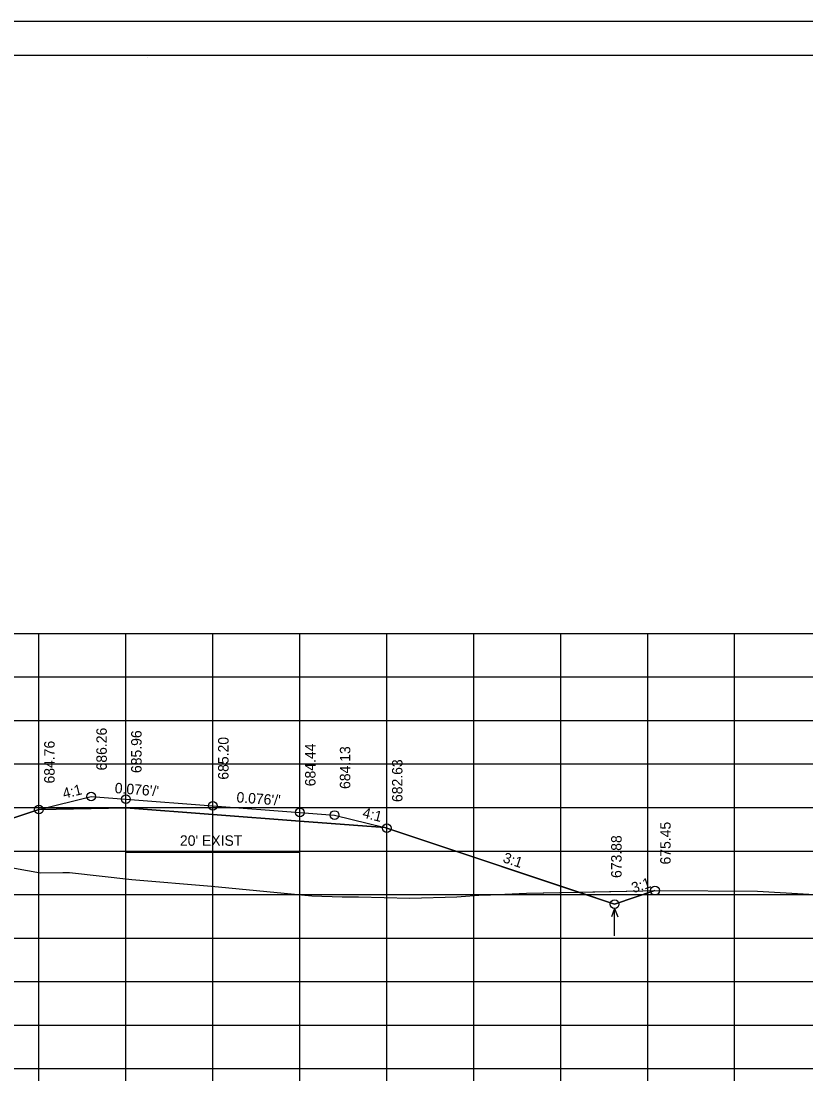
# Model space of a CAD drawing. Extents: x 1360146 to 1361431, y 631444 to 632352.
# Drawn here: x 1360296.7 to 1360386.9, y 631748.4 to 631870.8 of the extents above; entities that cross this region are included whole.
import ezdxf

# ---------------------------------------------------------------- set-up
doc = ezdxf.new("R2010")
doc.units = 0
for name, color, linetype in [('Default', 7, 'Continuous'), ('R_Alt Surface', 7, 'Continuous'), ('R_Axis', 7, 'Continuous'), ('R_Border', 7, 'Continuous'), ('R_Exist Surface', 7, 'Continuous'), ('R_Fin Surface', 7, 'Continuous'), ('R_Grid', 7, 'Continuous'), ('R_No Plot', 7, 'Continuous'), ('R_Water Annot', 7, 'Continuous'), ('R_Xsect Elev', 7, 'Continuous'), ('R_Xsect Slope', 7, 'Continuous')]:
    doc.layers.add(name, color=color, linetype=linetype)

msp = doc.modelspace()

# ---------------------------------------------------------------- linework, layer by layer
at = {"layer": 'Default'}
for p, q in [((1360308.77, 631774.69), (1360308.77, 631776.06)), ((1360328.77, 631774.69), (1360328.77, 631776.06)), ((1360308.77, 631775.35), (1360328.77, 631775.35))]:
    msp.add_line(p, q, dxfattribs=at)
at = {"layer": 'R_Alt Surface'}
msp.add_lwpolyline([(1360298.75, 631780.24), (1360308.77, 631780.44), (1360318.77, 631779.68), (1360328.77, 631778.92), (1360338.55, 631778.17)], dxfattribs=at)
at = {"layer": 'R_Axis'}
for p, q in [((1360178.77, 631750.48), (1360458.77, 631750.48)), ((1360298.77, 631749.08), (1360298.77, 631750.48)), ((1360308.77, 631749.08), (1360308.77, 631750.48)), ((1360318.77, 631749.08), (1360318.77, 631750.48)), ((1360328.77, 631749.08), (1360328.77, 631750.48)), ((1360338.77, 631749.08), (1360338.77, 631750.48)), ((1360348.77, 631749.08), (1360348.77, 631750.48)), ((1360358.77, 631749.08), (1360358.77, 631750.48)), ((1360368.77, 631749.08), (1360368.77, 631750.48)), ((1360378.77, 631749.08), (1360378.77, 631750.48))]:
    msp.add_line(p, q, dxfattribs=at)
at = {"layer": 'R_Border'}
for p, q in [((1360158.77, 631866.94), (1360474.95, 631866.94)), ((1360311.29, 631866.68), (1360311.29, 631866.68)), ((1360311.29, 631866.68), (1360311.29, 631866.68))]:
    msp.add_line(p, q, dxfattribs=at)
at = {"layer": 'R_Exist Surface'}
msp.add_lwpolyline([(1360290.37, 631774.5), (1360298.93, 631772.97), (1360301.53, 631773.02), (1360302.27, 631773.02), (1360309.44, 631772.21), (1360318.61, 631771.43), (1360330.16, 631770.31), (1360333.64, 631770.2), (1360335.53, 631770.21), (1360341.41, 631770.06), (1360346.84, 631770.23), (1360349.86, 631770.43), (1360350.68, 631770.45), (1360354.83, 631770.62), (1360368.2, 631770.91), (1360370.03, 631770.93), (1360381.41, 631770.85), (1360387.29, 631770.51)], dxfattribs=at)
at = {"layer": 'R_Fin Surface'}
msp.add_lwpolyline([(1360246.93, 631773.2), (1360262.28, 631768.08), (1360298.75, 631780.24), (1360298.77, 631780.24), (1360304.77, 631781.74), (1360308.77, 631781.44), (1360318.77, 631780.68), (1360328.77, 631779.92), (1360332.77, 631779.61), (1360338.55, 631778.17), (1360338.77, 631778.11), (1360364.97, 631769.38), (1360369.61, 631770.93)], dxfattribs=at)
at = {"layer": 'R_Grid'}
for p, q in [((1360178.77, 631800.48), (1360458.77, 631800.48)), ((1360298.77, 631750.48), (1360298.77, 631800.48)), ((1360308.77, 631750.48), (1360308.77, 631800.48)), ((1360318.77, 631750.48), (1360318.77, 631800.48)), ((1360328.77, 631750.48), (1360328.77, 631800.48)), ((1360338.77, 631750.48), (1360338.77, 631800.48)), ((1360348.77, 631750.48), (1360348.77, 631800.48)), ((1360358.77, 631750.48), (1360358.77, 631800.48)), ((1360368.77, 631750.48), (1360368.77, 631800.48)), ((1360378.77, 631750.48), (1360378.77, 631800.48)), ((1360178.77, 631795.48), (1360458.77, 631795.48)), ((1360178.77, 631790.48), (1360458.77, 631790.48)), ((1360178.77, 631785.48), (1360458.77, 631785.48)), ((1360178.77, 631780.48), (1360458.77, 631780.48)), ((1360178.77, 631775.48), (1360458.77, 631775.48)), ((1360178.77, 631770.48), (1360458.77, 631770.48)), ((1360178.77, 631765.48), (1360458.77, 631765.48)), ((1360178.77, 631760.48), (1360458.77, 631760.48)), ((1360178.77, 631755.48), (1360458.77, 631755.48)), ((1360178.77, 631750.48), (1360458.77, 631750.48))]:
    msp.add_line(p, q, dxfattribs=at)
at = {"layer": 'R_No Plot'}
msp.add_line((1360146.37, 631870.84), (1360479.7, 631870.84), dxfattribs=at)
for points in [[(1360146.36, 631870.84), (1360479.7, 631870.84), (1360479.7, 631657.5), (1360146.36, 631657.5)], [(1360392.69, 631866.94), (1360392.69, 631857.06), (1360428.42, 631857.06), (1360428.42, 631854.14), (1360451.62, 631854.14), (1360451.62, 631829.81), (1360474.95, 631829.81), (1360474.95, 631661.48), (1360158.77, 631661.48), (1360158.77, 631866.94)], [(1360360.86, 631770.75), (1360368.2, 631770.91), (1360369.61, 631770.93), (1360364.97, 631769.38)]]:
    msp.add_lwpolyline(points, close=True, dxfattribs=at)
msp.add_lwpolyline([(1360290.37, 631774.5), (1360298.93, 631772.97), (1360301.53, 631773.02), (1360302.27, 631773.02), (1360309.44, 631772.21), (1360318.61, 631771.43), (1360330.16, 631770.31), (1360333.64, 631770.2), (1360335.53, 631770.21), (1360341.41, 631770.06), (1360346.84, 631770.23), (1360349.86, 631770.43), (1360350.68, 631770.45), (1360354.83, 631770.62), (1360360.86, 631770.75), (1360338.77, 631778.11), (1360338.55, 631778.17), (1360328.77, 631778.92), (1360318.77, 631779.68), (1360308.77, 631780.44), (1360298.75, 631780.24), (1360281.82, 631774.6)], dxfattribs=at)
for centre in [(1360304.77, 631781.74), (1360308.77, 631781.44), (1360298.77, 631780.24), (1360318.77, 631780.68), (1360328.77, 631779.92), (1360332.77, 631779.61), (1360338.77, 631778.11), (1360369.61, 631770.93), (1360364.97, 631769.38)]:
    msp.add_circle(centre, 0.5, dxfattribs=at)
at = {"layer": 'R_Water Annot'}
for p, q in [((1360364.97, 631768.88), (1360364.62, 631767.92)), ((1360364.97, 631765.74), (1360364.97, 631768.88)), ((1360364.97, 631768.88), (1360365.32, 631767.92))]:
    msp.add_line(p, q, dxfattribs=at)

# ---------------------------------------------------------------- texts
at = {"layer": 'Default'}
msp.add_text("20' EXIST", height=1.2, dxfattribs=at).set_placement((1360314.98, 631776.08))
at = {"layer": 'R_Xsect Elev'}
for s, p in [('686.26', (1360306.57, 631784.74)), ('685.96', (1360310.57, 631784.44)), ('684.76', (1360300.57, 631783.24)), ('685.20', (1360320.57, 631783.68)), ('684.44', (1360330.57, 631782.92)), ('684.13', (1360334.57, 631782.61)), ('682.63', (1360340.57, 631781.11)), ('675.45', (1360371.41, 631773.93)), ('673.88', (1360365.77, 631772.38))]:
    msp.add_text(s, height=1.2, rotation=90, dxfattribs=at).set_placement(p)
at = {"layer": 'R_Xsect Slope'}
for s, rotation, p in [('4:1', 14.0362, (1360301.65, 631781.48)), ("0.076'/'", 355.6497, (1360307.45, 631782.14)), ("0.076'/'", 355.6497, (1360321.45, 631781.08)), ('4:1', 345.9638, (1360335.89, 631779.35)), ('3:1', 341.5651, (1360352.03, 631774.22)), ('3:1', 18.4349, (1360367.13, 631770.63))]:
    msp.add_text(s, height=1.2, rotation=rotation, dxfattribs=at).set_placement(p)

doc.saveas('drawing.dxf')
